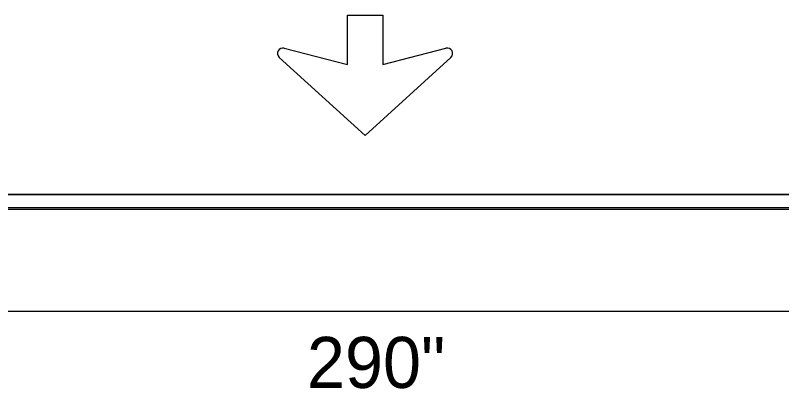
# Model space of a CAD drawing. Extents: x 2149934 to 2150188, y 145113 to 145238.
# Drawn here: x 2149949.1 to 2149957.85, y 145135.9 to 145140.17 of the extents above; entities that cross this region are included whole.
import ezdxf

# ---------------------------------------------------------------- set-up
doc = ezdxf.new("R2010")
doc.units = 0
for name, color, linetype in [('GSBWFILL', 7, 'Continuous'), ('GSCOLORFILL', 7, 'Continuous'), ('GSDIMS', 7, 'Continuous'), ('GSOUTLINE', 7, 'Continuous')]:
    doc.layers.add(name, color=color, linetype=linetype)

msp = doc.modelspace()

# ---------------------------------------------------------------- linework, layer by layer
at = {"layer": 'GSBWFILL'}
for p, q in [((2149965.5964, 145138.1202), (2149940.598, 145138.1202)), ((2149940.598, 145137.9536), (2149965.5964, 145137.9536))]:
    msp.add_line(p, q, dxfattribs=at)
for points in [[(2149952.1735, 145139.7918), (2149952.8935, 145139.6069), (2149952.8935, 145140.1675), (2149953.2992, 145140.1675), (2149953.2992, 145139.6069), (2149954.0192, 145139.7918)], [(2149954.0758, 145139.6868), (2149953.0963, 145138.7954), (2149952.1168, 145139.6868)]]:
    msp.add_lwpolyline(points, dxfattribs=at)
for centre, start, end in [((2149952.1582, 145139.7323), 75.59252, 227.69521), ((2149954.0345, 145139.7323), 312.30479, 104.40748)]:
    msp.add_arc(centre, 0.0615, start, end, dxfattribs=at)
at = {"layer": 'GSCOLORFILL'}
for p, q in [((2149965.5964, 145138.1202), (2149940.598, 145138.1202)), ((2149940.5963, 145137.9536), (2149965.5964, 145137.9536)), ((2149965.5964, 145137.9702), (2149940.5965, 145137.9702)), ((2149940.5965, 145137.9536), (2149965.5964, 145137.9536)), ((2149940.598, 145137.9536), (2149965.5964, 145137.9536))]:
    msp.add_line(p, q, dxfattribs=at)
for points in [[(2149952.1735, 145139.7918), (2149952.8935, 145139.6069), (2149952.8935, 145140.1675), (2149953.2992, 145140.1675), (2149953.2992, 145139.6069), (2149954.0192, 145139.7918)], [(2149954.0758, 145139.6868), (2149953.0963, 145138.7954), (2149952.1168, 145139.6868)]]:
    msp.add_lwpolyline(points, dxfattribs=at)
for centre, start, end in [((2149952.1582, 145139.7323), 75.59252, 227.69521), ((2149954.0345, 145139.7323), 312.30479, 104.40748)]:
    msp.add_arc(centre, 0.0615, start, end, dxfattribs=at)
at = {"layer": 'GSDIMS'}
msp.add_line((2149941.013, 145136.7869), (2149965.1797, 145136.7869), dxfattribs=at)
at = {"layer": 'GSOUTLINE'}
for p, q in [((2149940.5963, 145138.1202), (2149965.5964, 145138.1202)), ((2149940.5963, 145137.9536), (2149965.5964, 145137.9536))]:
    msp.add_line(p, q, dxfattribs=at)
for points in [[(2149952.1735, 145139.7918), (2149952.8935, 145139.6069), (2149952.8935, 145140.1675), (2149953.2992, 145140.1675), (2149953.2992, 145139.6069), (2149954.0192, 145139.7918)], [(2149954.0758, 145139.6868), (2149953.0963, 145138.7954), (2149952.1168, 145139.6868)]]:
    msp.add_lwpolyline(points, dxfattribs=at)
for centre, start, end in [((2149952.1582, 145139.7323), 75.59252, 227.69521), ((2149954.0345, 145139.7323), 312.30479, 104.40748)]:
    msp.add_arc(centre, 0.0615, start, end, dxfattribs=at)

# ---------------------------------------------------------------- texts
at = {"layer": 'GSDIMS'}
msp.add_text('290"', height=0.58333, dxfattribs=at).set_placement((2149952.4328, 145135.9118))

doc.saveas('drawing.dxf')
